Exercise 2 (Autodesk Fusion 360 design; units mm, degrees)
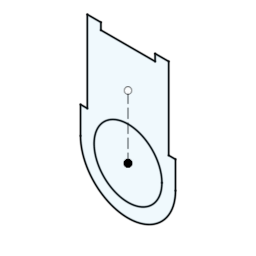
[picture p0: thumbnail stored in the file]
sketch "Sketch1" plane through (0, 0, 0) normal (0, 0, 1) x axis (1, 0, 0)
  line L1 (35, 20) -> (35, 0)
  line L2 (30, 20) -> (35, 20)
  line L3 (30, 80) -> (30, 20)
  line L4 (20, 80) -> (30, 80)
  line L5 (20, 75) -> (20, 80)
  line L6 (-20, 75) -> (20, 75)
  line L7 (-20, 80) -> (-20, 75)
  line L8 (-30, 80) -> (-20, 80)
  line L9 (-30, 20) -> (-30, 80)
  line L10 (-35, 20) -> (-30, 20)
  line L11 (-35, 0) -> (-35, 20)
  line L12 (0, 46.4145) -> (0, 0)
  circle C1 centre (0, 0) radius 25
  arc A1 centre (0, 0) radius 35 clockwise from (35, 0) to (-35, 0)
  point P1 (0, 0)
  point P2 (0, 0)
  point P3 (0, 0)
  point P16 (0, 0)
  point P5 (35, 0)
  point P6 (35, 20)
  point P7 (30, 20)
  point P8 (30, 80)
  point P9 (20, 80)
  point P10 (20, 75)
  point P11 (-20, 75)
  point P12 (-20, 80)
  coincident P1 P2
  coincident P2 P3
  tangent A1 L1
  vertical L1
  perpendicular L1 L2
  perpendicular L2 L3
  perpendicular L3 L4
  perpendicular L2 L5
  perpendicular L3 L6
  perpendicular L6 L7
  perpendicular L7 L8
  perpendicular L8 L9
  perpendicular L9 L10
  tangent A1 L11
  equal L4 L8
  equal L2 L10
  equal L1 L11
  coincident P3 P16
  vertical L12
  equal L3 L9
  symmetric L3 L9 L12
  dimension "d1" diameter C1 = 50
  dimension "d2" radius A1 = 35
  dimension "d3" distance P5 P6 = 20
  dimension "d4" distance P7 P8 = 60
  dimension "d5" distance P8 P9 = 10
  dimension "d6" distance P10 P11 = 40
  dimension "d7" distance P11 P12 = 5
